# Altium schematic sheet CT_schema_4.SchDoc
size 287 x 169 mm
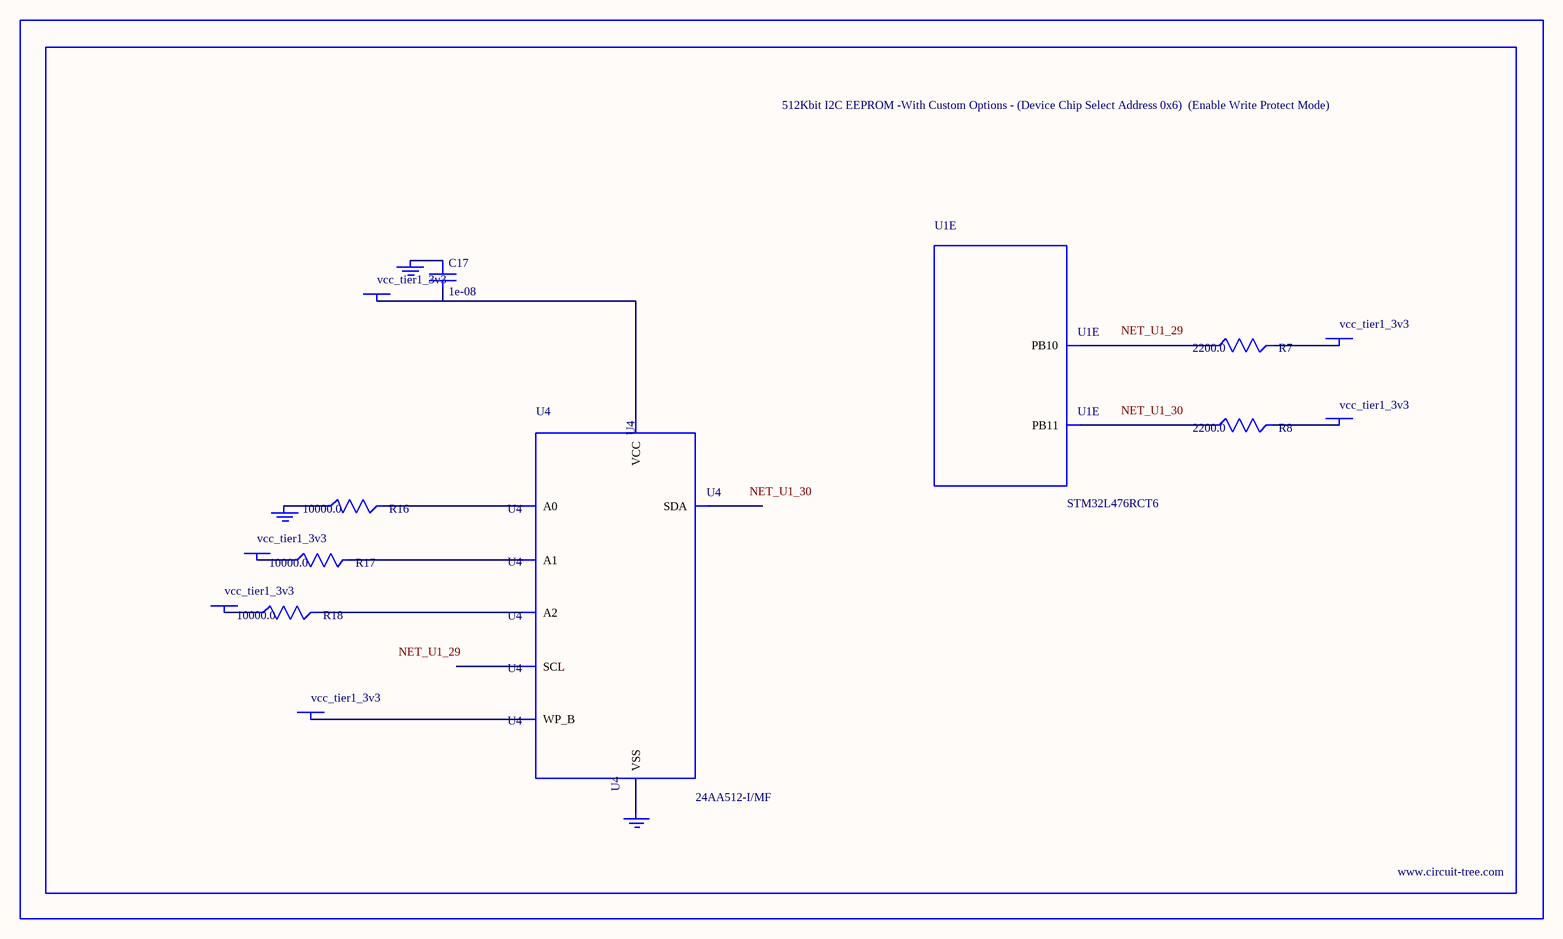
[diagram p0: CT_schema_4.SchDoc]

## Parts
BORDER3  (no value)
C17  1e-08  [C0402]
GND_INSTANCE_3_0  (no value)
GND_INSTANCE_3_1  (no value)
GND_INSTANCE_3_2  (no value)
POWER_INSTANCE_3_0  vcc_tier1_3v3
POWER_INSTANCE_3_1  vcc_tier1_3v3
POWER_INSTANCE_3_2  vcc_tier1_3v3
POWER_INSTANCE_3_3  vcc_tier1_3v3
POWER_INSTANCE_3_4  vcc_tier1_3v3
POWER_INSTANCE_3_5  vcc_tier1_3v3
R7  2200.0  [R0603]
R8  2200.0  [R0603]
R16  10000.0  [R0603]
R17  10000.0  [R0603]
R18  10000.0  [R0603]
U1  STM32L476RCT6  [LQFP64]  (part E of 6)
U4  24AA512-I/MF  [DFN8-S]

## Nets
NetC17_1: C17.1 GND_INSTANCE_3_1.0(GND)
NetC17_2: C17.2 POWER_INSTANCE_3_3.0(PWR) U4.8(VCC)
NetGND_INSTANCE_3_0_0: GND_INSTANCE_3_0.0(GND) R16.1
NetGND_INSTANCE_3_2_0: GND_INSTANCE_3_2.0(GND) U4.4(VSS)
NetPOWER_INSTANCE_3_0_0: POWER_INSTANCE_3_0.0(PWR) R17.1
NetPOWER_INSTANCE_3_1_0: POWER_INSTANCE_3_1.0(PWR) R18.1
NetPOWER_INSTANCE_3_2_0: POWER_INSTANCE_3_2.0(PWR) U4.7(WP_B)
NetPOWER_INSTANCE_3_4_0: POWER_INSTANCE_3_4.0(PWR) R7.2
NetPOWER_INSTANCE_3_5_0: POWER_INSTANCE_3_5.0(PWR) R8.2
NetR7_1: R7.1 U1.29(PB10)
NetR8_1: R8.1 U1.30(PB11)
NetR16_2: R16.2 U4.1(A0)
NetR17_2: R17.2 U4.2(A1)
NetR18_2: R18.2 U4.3(A2)

Not connected (* = marked no-connect by the designer): U4 5(SDA) 6(SCL)

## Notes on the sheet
- Labels drawn without touching a wire or pin: NET_U1_29, NET_U1_30

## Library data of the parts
BORDER3 = BORDER_PAGE3
C17 = C0402C103K3RAC
GND_INSTANCE_3_0-GND_INSTANCE_3_2 = GND
POWER_INSTANCE_3_0-POWER_INSTANCE_3_5 = PWR
R7 R8 = RC0603JR-072K2L
R16-R18 = RC0603JR-0710KL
